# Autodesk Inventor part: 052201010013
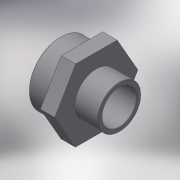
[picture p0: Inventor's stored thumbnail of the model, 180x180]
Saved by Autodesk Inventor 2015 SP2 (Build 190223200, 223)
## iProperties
Created: 2017-10
Part Number: 052201010013
Material: Generic
Description: PLASSON SOCKET NIPPLE THR. P 1"-1.1/4"
Document SubType Name: Modeling
Designer: KIM
Density: 1 g/cm^3
Appearance: Default
Author: KIM
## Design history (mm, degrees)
derived "052201.ipt"
feature "Solid1::052201.ipt"
tag "TaggingFeature1"
body "Solid1"
other parameters: "d0" = 57, "d2" = 55, "d13" = 0, "d14" = 0.38952, "d17" = 18, "d18" = 26.4, "d19" = 48.10572, "d20" = 38.952, "d21" = 33.249, "d22" = 14.4, "d23" = 37.0044, "d24" = 26.5992, "d25" = 22, "d26" = -18, "G_" = 38.952, "R_" = 33.249, "C_" = 55, "lt_1" = 18, "lt_" = 22, "H_" = 57
